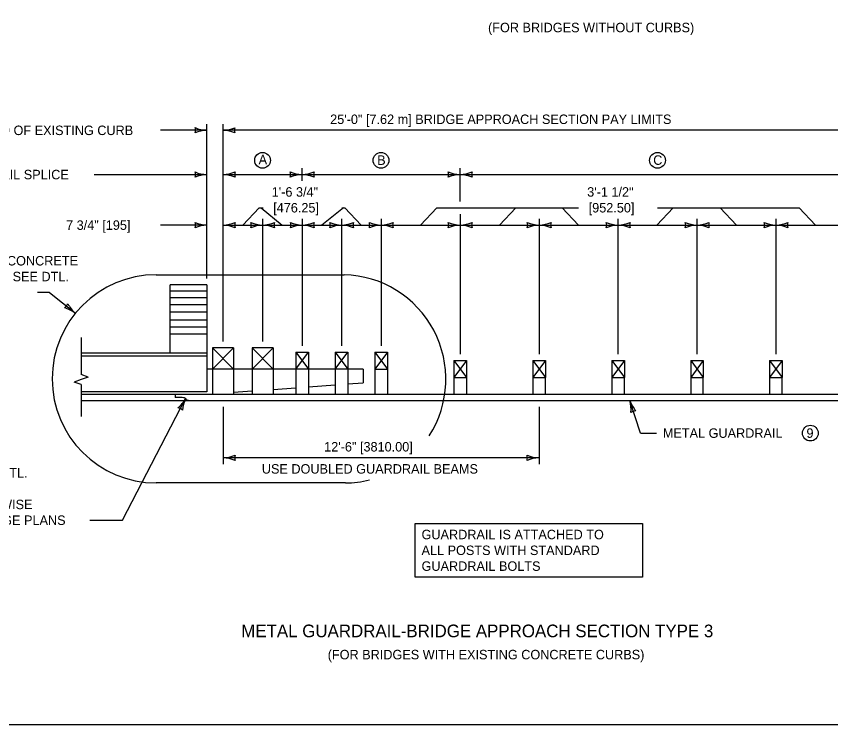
# Model space of a CAD drawing. Extents: x 49991.4 to 50021, y 49987.6 to 50011.4.
# Drawn here: x 50008.83 to 50013.99, y 49987.8 to 49992.28 of the extents above; entities that cross this region are included whole.
import ezdxf

# ---------------------------------------------------------------- set-up
doc = ezdxf.new("R2010")
doc.units = 0
for name, color, linetype in [('Level 1', 7, 'Continuous'), ('Level 2', 7, 'Continuous'), ('Level 3', 7, 'Continuous'), ('Level 4', 7, 'Continuous'), ('Level 6', 7, 'Continuous')]:
    doc.layers.add(name, color=color, linetype=linetype)

msp = doc.modelspace()

# ---------------------------------------------------------------- linework, layer by layer
at = {"layer": 'Level 1'}
for p, q in [((50010.0391, 49990.584), (50009.807, 49990.584)), ((50009.807, 49990.151), (50009.807, 49990.584)), ((50010.0391, 49990.584), (50010.0391, 49989.9066)), ((50010.0391, 49990.5438), (50009.807, 49990.5438)), ((50010.0391, 49990.5015), (50009.807, 49990.5015)), ((50010.0391, 49990.4569), (50009.807, 49990.4569)), ((50010.0391, 49990.4106), (50009.807, 49990.4106)), ((50010.0391, 49990.3606), (50009.807, 49990.3606)), ((50010.0391, 49990.316), (50009.807, 49990.316)), ((50010.0391, 49990.2718), (50009.807, 49990.2718)), ((50010.0391, 49990.151), (50009.244, 49990.151)), ((50010.2092, 49990.1843), (50010.0758, 49990.1843)), ((50010.0758, 49990.1843), (50010.0758, 49989.8909)), ((50010.0758, 49990.051), (50010.2092, 49990.1843)), ((50010.0758, 49990.1843), (50010.2092, 49990.051)), ((50010.2092, 49990.1843), (50010.2092, 49989.8909)), ((50010.4594, 49990.1844), (50010.326, 49990.1844)), ((50010.326, 49990.1844), (50010.326, 49989.8909)), ((50010.326, 49990.051), (50010.4594, 49990.1844)), ((50010.326, 49990.1844), (50010.4594, 49990.051)), ((50010.4594, 49990.1844), (50010.4594, 49989.8909)), ((50010.6028, 49990.1577), (50010.6028, 49989.8909)), ((50010.6028, 49990.1577), (50010.6829, 49990.1577)), ((50010.6028, 49990.051), (50010.6829, 49990.1577)), ((50010.6028, 49990.1577), (50010.6829, 49990.051)), ((50010.6829, 49990.1577), (50010.6829, 49989.8909)), ((50010.853, 49990.157), (50010.853, 49989.8909)), ((50010.853, 49990.157), (50010.933, 49990.157)), ((50010.853, 49990.051), (50010.933, 49990.157)), ((50010.853, 49990.157), (50010.933, 49990.051)), ((50010.933, 49990.157), (50010.933, 49989.8909)), ((50011.1031, 49990.1577), (50011.1031, 49990.051)), ((50011.1031, 49990.1577), (50011.1832, 49990.1577)), ((50011.1832, 49990.1577), (50011.1031, 49990.051)), ((50011.1031, 49990.1577), (50011.1832, 49990.051)), ((50011.1832, 49990.1577), (50011.1832, 49990.051)), ((50010.0391, 49990.1315), (50009.244, 49990.1315)), ((50011.6034, 49990.1043), (50011.6034, 49989.9976)), ((50011.6034, 49990.1043), (50011.6835, 49990.1043)), ((50011.6835, 49990.1043), (50011.6034, 49989.9976)), ((50011.6034, 49990.1043), (50011.6835, 49989.9976)), ((50011.6835, 49990.1043), (50011.6835, 49989.9976)), ((50012.1038, 49990.1043), (50012.1038, 49989.9976)), ((50012.1038, 49990.1043), (50012.1838, 49990.1043)), ((50012.1838, 49990.1043), (50012.1038, 49989.9976)), ((50012.1038, 49990.1043), (50012.1838, 49989.9976)), ((50012.1838, 49990.1043), (50012.1838, 49989.9976)), ((50012.604, 49990.1043), (50012.604, 49989.9976)), ((50012.604, 49990.1043), (50012.6841, 49990.1043)), ((50012.6841, 49990.1043), (50012.604, 49989.9976)), ((50012.604, 49990.1043), (50012.6841, 49989.9976)), ((50012.6841, 49990.1043), (50012.6841, 49989.9976)), ((50013.1043, 49990.1043), (50013.1043, 49989.9976)), ((50013.1043, 49990.1043), (50013.1844, 49990.1043)), ((50013.1844, 49990.1043), (50013.1043, 49989.9976)), ((50013.1043, 49990.1043), (50013.1844, 49989.9976)), ((50013.1844, 49990.1043), (50013.1844, 49989.9976)), ((50013.6046, 49990.1043), (50013.6046, 49989.9976)), ((50013.6046, 49990.1043), (50013.6847, 49990.1043)), ((50013.6847, 49990.1043), (50013.6046, 49989.9976)), ((50013.6046, 49990.1043), (50013.6847, 49989.9976)), ((50013.6847, 49990.1043), (50013.6847, 49989.9976)), ((50011.0289, 49990.051), (50010.0391, 49990.051)), ((50011.0289, 49990.051), (50011.0289, 49989.9642)), ((50011.1031, 49990.051), (50011.1832, 49990.051)), ((50011.1031, 49990.051), (50011.1031, 49989.8909)), ((50011.1832, 49990.051), (50011.1832, 49989.8909)), ((50011.6034, 49989.9976), (50011.6835, 49989.9976)), ((50011.6034, 49989.9976), (50011.6034, 49989.8909)), ((50011.6835, 49989.9976), (50011.6835, 49989.8909)), ((50012.1038, 49989.9976), (50012.1838, 49989.9976)), ((50012.1038, 49989.9976), (50012.1038, 49989.8909)), ((50012.1838, 49989.8909), (50012.1838, 49989.9976)), ((50012.604, 49989.9979), (50012.604, 49989.8909)), ((50012.604, 49989.9976), (50012.6841, 49989.9976)), ((50012.6841, 49989.8909), (50012.6841, 49989.9976)), ((50013.1043, 49989.9979), (50013.1043, 49989.8909)), ((50013.1043, 49989.9976), (50013.1844, 49989.9976)), ((50013.1844, 49989.8909), (50013.1844, 49989.9976)), ((50013.6046, 49989.9979), (50013.6046, 49989.8909)), ((50013.6046, 49989.9976), (50013.6847, 49989.9976)), ((50013.6847, 49989.8909), (50013.6847, 49989.9976)), ((50010.6829, 49989.9386), (50010.853, 49989.9512)), ((50010.933, 49989.9571), (50011.0289, 49989.9642)), ((50010.0391, 49989.9066), (50009.2441, 49989.9066)), ((50009.2441, 49989.8909), (50014.424, 49989.8909)), ((50009.839, 49989.8909), (50009.839, 49989.8702)), ((50010.0391, 49989.8909), (50010.0758, 49989.8936)), ((50010.2092, 49989.9035), (50010.326, 49989.9121)), ((50010.4594, 49989.922), (50010.6028, 49989.9326)), ((50009.2441, 49989.8508), (50014.424, 49989.8508)), ((50009.874, 49989.8702), (50009.839, 49989.8702))]:
    msp.add_line(p, q, dxfattribs=at)
msp.add_lwpolyline([(49999.3835, 49998.9992), (50016.7501, 49998.9992), (50016.7501, 49987.7988), (49999.3835, 49987.7988)], close=True, dxfattribs=at)
msp.add_spline([(50009.9238, 49989.8508), (50009.9175, 49989.8527), (50009.9113, 49989.8568), (50009.9061, 49989.863), (50009.902, 49989.8671), (50009.8927, 49989.8691), (50009.874, 49989.8702)], degree=3, dxfattribs=at)
at = {"layer": 'Level 2'}
msp.add_lwpolyline([(50011.3597, 49989.0731), (50012.7994, 49989.0731), (50012.7994, 49988.7331), (50011.3597, 49988.7331)], close=True, dxfattribs=at)
for centre in [(50010.3927, 49991.3723), (50011.1431, 49991.3723), (50012.8942, 49991.3723), (50013.8621, 49989.6453)]:
    msp.add_circle(centre, 0.05, dxfattribs=at)
at = {"layer": 'Level 3'}
for p, q in [((50010.0392, 49990.624), (50010.0392, 49991.6024)), ((50010.1426, 49990.2243), (50010.1426, 49991.6024)), ((50010.0392, 49991.5624), (50009.7455, 49991.5624)), ((50014.1448, 49991.5624), (50010.1426, 49991.5624)), ((50009.325, 49991.2823), (50010.0392, 49991.2823)), ((50010.1426, 49991.2823), (50010.6429, 49991.2823)), ((50010.6429, 49991.2423), (50010.6429, 49991.3223)), ((50010.6429, 49991.2823), (50011.6435, 49991.2823)), ((50011.6435, 49991.1123), (50011.6435, 49991.3223)), ((50011.6435, 49991.2823), (50014.1447, 49991.2823)), ((50010.3702, 49991.0723), (50010.2667, 49990.9623)), ((50010.3702, 49991.0723), (50010.3962, 49991.0723)), ((50010.3832, 49991.0723), (50010.517, 49990.9623)), ((50010.9051, 49991.0723), (50010.7676, 49990.9623)), ((50010.8957, 49991.0723), (50010.9144, 49991.0723)), ((50010.9144, 49991.0723), (50011.0179, 49990.9623)), ((50011.4967, 49991.0723), (50011.3932, 49990.9623)), ((50011.4967, 49991.0723), (50012.3943, 49991.0723)), ((50011.9969, 49991.0723), (50011.8934, 49990.9623)), ((50012.2904, 49991.0723), (50012.3939, 49990.9623)), ((50012.9929, 49991.0723), (50012.8894, 49990.9623)), ((50012.8938, 49991.0723), (50013.7912, 49991.0723)), ((50013.2909, 49991.0723), (50013.3944, 49990.9623)), ((50013.7912, 49991.0723), (50013.8947, 49990.9623)), ((50011.6434, 49991.0323), (50011.6434, 49990.1444)), ((50010.3927, 49991.0023), (50010.3927, 49990.2244)), ((50010.6429, 49991.0023), (50010.6429, 49990.1977)), ((50010.893, 49991.0023), (50010.893, 49990.197)), ((50011.1431, 49991.0023), (50011.1431, 49990.1977)), ((50012.1437, 49991.0023), (50012.1437, 49990.1444)), ((50012.6439, 49991.0023), (50012.6439, 49990.1444)), ((50013.1442, 49991.0023), (50013.1442, 49990.1444)), ((50013.6444, 49991.0023), (50013.6444, 49990.1444)), ((50010.0392, 49990.9623), (50009.7467, 49990.9623)), ((50010.1426, 49990.9623), (50010.3927, 49990.9623)), ((50010.3927, 49990.9623), (50010.6429, 49990.9623)), ((50010.6429, 49990.9623), (50010.893, 49990.9623)), ((50010.893, 49990.9623), (50011.1431, 49990.9623)), ((50011.1431, 49990.9623), (50011.6434, 49990.9623)), ((50011.6434, 49990.9623), (50012.1437, 49990.9623)), ((50012.1437, 49990.9623), (50012.6439, 49990.9623)), ((50012.6439, 49990.9623), (50013.1442, 49990.9623)), ((50013.1442, 49990.9623), (50013.6444, 49990.9623)), ((50013.6444, 49990.9623), (50014.1447, 49990.9623)), ((50009.0432, 49990.5366), (50008.9661, 49990.5366)), ((50009.0432, 49990.5366), (50009.2072, 49990.4038)), ((50009.5053, 49989.0937), (50009.9055, 49989.8637)), ((50012.7857, 49989.6453), (50012.7188, 49989.8508)), ((50010.1426, 49989.8108), (50010.1426, 49989.4487)), ((50012.1438, 49989.8108), (50012.1438, 49989.4487)), ((50012.7857, 49989.6453), (50012.8881, 49989.6453)), ((50012.1438, 49989.4887), (50010.1426, 49989.4887)), ((50009.2989, 49989.0937), (50009.5053, 49989.0937))]:
    msp.add_line(p, q, dxfattribs=at)
for centre, radius, start, end in [((50009.9142, 49991.5636), 0.0534, 341.5738, 17.2962), ((50010.0482, 49991.3354), 0.2271, 92.2623, 111.5122), ((50010.0503, 49991.7788), 0.2167, 246.891, 267.0745), ((50010.1314, 49991.7892), 0.2271, 272.8273, 292.0772), ((50010.1337, 49991.3458), 0.2167, 67.456, 87.6395), ((50010.2676, 49991.5624), 0.0534, 162.1388, 197.8612), ((50010.0481, 49991.4989), 0.2167, 247.456, 267.6395), ((50009.9142, 49991.2823), 0.0534, 342.1388, 17.8612), ((50010.0504, 49991.0554), 0.2271, 92.8273, 112.0772), ((50010.1311, 49991.5151), 0.2331, 272.8273, 292.0772), ((50010.1334, 49991.0601), 0.2224, 67.456, 87.6395), ((50010.2709, 49991.2823), 0.0548, 162.1388, 197.8612), ((50010.652, 49991.5046), 0.2224, 247.456, 267.6395), ((50010.5146, 49991.2823), 0.0548, 342.1388, 17.8612), ((50010.6544, 49991.0495), 0.2331, 92.8273, 112.0772), ((50010.6314, 49991.5151), 0.2331, 272.8273, 292.0772), ((50010.6337, 49991.0601), 0.2224, 67.456, 87.6395), ((50010.7711, 49991.2823), 0.0548, 162.1388, 197.8612), ((50011.6527, 49991.5046), 0.2224, 247.456, 267.6395), ((50011.5152, 49991.2823), 0.0548, 342.1388, 17.8612), ((50011.655, 49991.0495), 0.2331, 92.8273, 112.0772), ((50011.632, 49991.5151), 0.2331, 272.8273, 292.0772), ((50011.6343, 49991.0601), 0.2224, 67.456, 87.6395), ((50011.7718, 49991.2823), 0.0548, 162.1388, 197.8612), ((50010.0481, 49991.1789), 0.2167, 247.456, 267.6395), ((50009.9142, 49990.9623), 0.0534, 342.1388, 17.8612), ((50010.1311, 49991.1951), 0.2331, 272.8273, 292.0772), ((50010.2709, 49990.9623), 0.0548, 162.1388, 197.8612), ((50010.4017, 49991.1788), 0.2167, 247.456, 267.6395), ((50010.2677, 49990.9623), 0.0534, 342.1388, 17.8612), ((50010.3812, 49991.1951), 0.2331, 272.8273, 292.0772), ((50010.521, 49990.9623), 0.0548, 162.1388, 197.8612), ((50010.6518, 49991.1788), 0.2167, 247.456, 267.6395), ((50010.5179, 49990.9623), 0.0534, 342.1388, 17.8612), ((50010.6314, 49991.1951), 0.2331, 272.8273, 292.0772), ((50010.7711, 49990.9623), 0.0548, 162.1388, 197.8612), ((50010.9019, 49991.1788), 0.2167, 247.456, 267.6395), ((50010.768, 49990.9623), 0.0534, 342.1388, 17.8612), ((50010.8815, 49991.1951), 0.2331, 272.8273, 292.0772), ((50011.0213, 49990.9623), 0.0548, 162.1388, 197.8612), ((50011.1521, 49991.1788), 0.2167, 247.456, 267.6395), ((50011.0181, 49990.9623), 0.0534, 342.1388, 17.8612), ((50011.1316, 49991.1951), 0.2331, 272.8273, 292.0772), ((50011.2714, 49990.9623), 0.0548, 162.1388, 197.8612), ((50011.6523, 49991.1788), 0.2167, 247.456, 267.6395), ((50011.5184, 49990.9623), 0.0534, 342.1388, 17.8612), ((50011.6319, 49991.1951), 0.2331, 272.8273, 292.0772), ((50011.7717, 49990.9623), 0.0548, 162.1388, 197.8612), ((50012.1526, 49991.1788), 0.2167, 247.456, 267.6395), ((50012.0187, 49990.9623), 0.0534, 342.1388, 17.8612), ((50012.1322, 49991.1951), 0.2331, 272.8273, 292.0772), ((50012.2719, 49990.9623), 0.0548, 162.1388, 197.8612), ((50012.6528, 49991.1788), 0.2167, 247.456, 267.6395), ((50012.5189, 49990.9623), 0.0534, 342.1388, 17.8612), ((50012.6324, 49991.1951), 0.2331, 272.8273, 292.0772), ((50012.7722, 49990.9623), 0.0548, 162.1388, 197.8612), ((50013.1531, 49991.1788), 0.2167, 247.456, 267.6395), ((50013.0192, 49990.9623), 0.0534, 342.1388, 17.8612), ((50013.1327, 49991.1951), 0.2331, 272.8273, 292.0772), ((50013.2725, 49990.9623), 0.0548, 162.1388, 197.8612), ((50013.6534, 49991.1788), 0.2167, 247.456, 267.6395), ((50013.5195, 49990.9623), 0.0534, 342.1388, 17.8612), ((50013.6329, 49991.1951), 0.2331, 272.8273, 292.0772), ((50013.7727, 49990.9623), 0.0548, 162.1388, 197.8612), ((50010.0504, 49990.7354), 0.2271, 92.8273, 112.0772), ((50010.1334, 49990.7401), 0.2224, 67.456, 87.6395), ((50010.4039, 49990.7355), 0.2271, 92.8273, 112.0772), ((50010.3836, 49990.7401), 0.2224, 67.456, 87.6395), ((50010.6541, 49990.7355), 0.2271, 92.8273, 112.0772), ((50010.6337, 49990.7401), 0.2224, 67.456, 87.6395), ((50010.9042, 49990.7355), 0.2271, 92.8273, 112.0772), ((50010.8838, 49990.7401), 0.2224, 67.456, 87.6395), ((50011.1543, 49990.7355), 0.2271, 92.8273, 112.0772), ((50011.134, 49990.7401), 0.2224, 67.456, 87.6395), ((50011.6546, 49990.7355), 0.2271, 92.8273, 112.0772), ((50011.6342, 49990.7401), 0.2224, 67.456, 87.6395), ((50012.1549, 49990.7355), 0.2271, 92.8273, 112.0772), ((50012.1345, 49990.7401), 0.2224, 67.456, 87.6395), ((50012.6551, 49990.7355), 0.2271, 92.8273, 112.0772), ((50012.6348, 49990.7401), 0.2224, 67.456, 87.6395), ((50013.1554, 49990.7355), 0.2271, 92.8273, 112.0772), ((50013.135, 49990.7401), 0.2224, 67.456, 87.6395), ((50013.6556, 49990.7355), 0.2271, 92.8273, 112.0772), ((50013.6353, 49990.7401), 0.2224, 67.456, 87.6395), ((50009.1076, 49990.4845), 0.0548, 303.1426, 338.865), ((50009.3541, 49990.5707), 0.2223, 208.4598, 228.6433), ((50009.0697, 49990.2157), 0.233, 53.8311, 73.081), ((50009.7175, 49989.9715), 0.2167, 309.9961, 330.1796), ((50010.112, 49989.769), 0.2271, 155.3674, 174.6172), ((50012.5101, 49989.7923), 0.2167, 355.4765, 15.66), ((50012.9311, 49989.9317), 0.2271, 200.8478, 220.0976), ((50009.8479, 49989.7528), 0.0534, 44.6789, 80.4012), ((50012.7575, 49989.732), 0.0534, 90.1593, 125.8816), ((50010.1311, 49989.7215), 0.2331, 272.8273, 292.0772), ((50010.1334, 49989.2664), 0.2225, 67.456, 87.6395), ((50010.2709, 49989.4887), 0.0548, 162.1388, 197.8612), ((50012.153, 49989.7109), 0.2225, 247.456, 267.6395), ((50012.0155, 49989.4887), 0.0548, 342.1388, 17.8612), ((50012.1553, 49989.2558), 0.2331, 92.8273, 112.0772)]:
    msp.add_arc(centre, radius, start, end, dxfattribs=at)
at = {"layer": 'Level 4'}
for p, q in [((50009.7196, 49990.6483), (50010.9094, 49990.6483)), ((50010.9185, 49989.3297), (50009.7196, 49989.3297))]:
    msp.add_line(p, q, dxfattribs=at)
for centre, radius, start, end in [((50009.7196, 49989.989), 0.6593, 90, 270), ((50010.8923, 49989.9869), 0.6615, 327.2133, 88.5245), ((50010.9185, 49989.9393), 0.6096, 270, 284.3678)]:
    msp.add_arc(centre, radius, start, end, dxfattribs=at)
at = {"layer": 'Level 6'}
for p, q in [((50009.244, 49990.251), (50009.244, 49990.0159)), ((50009.2886, 49990.0001), (50009.244, 49990.0159)), ((50009.2886, 49990.0001), (50009.2441, 49989.9843)), ((50009.2441, 49989.9843), (50009.1995, 49989.9685)), ((50009.2441, 49989.9527), (50009.1995, 49989.9685)), ((50009.2441, 49989.9527), (50009.2441, 49989.7506))]:
    msp.add_line(p, q, dxfattribs=at)

# ---------------------------------------------------------------- texts
at = {"layer": 'Level 2'}
for s, height, p in [('(FOR BRIDGES WITHOUT CURBS)', 0.06, (50011.8208, 49992.1835)), ('25\'-0" [7.62 m] BRIDGE APPROACH SECTION PAY LIMITS', 0.06, (50010.8207, 49991.6024)), ('END OF EXISTING CURB', 0.06, (50008.6237, 49991.5324)), ('A', 0.06, (50010.3676, 49991.3475)), ('B', 0.06, (50011.1186, 49991.3436)), ('C', 0.06, (50012.8671, 49991.344)), ('¡ RAIL SPLICE', 0.06, (50008.6304, 49991.2523)), ('1\'-6 3/4"', 0.06, (50010.4507, 49991.1423)), ('3\'-1 1/2"', 0.06, (50012.4488, 49991.1423)), ('[476.25]', 0.06, (50010.46, 49991.0423)), ('[952.50]', 0.06, (50012.4581, 49991.0423)), ('7 3/4" [195]', 0.06, (50009.1482, 49990.9323)), ('FOR TAPERED CONCRETE', 0.06, (50008.1808, 49990.7066)), ('CURB DETAILS, SEE DTL.', 0.06, (50008.1808, 49990.6066)), ('METAL GUARDRAIL', 0.06, (50012.9281, 49989.6153)), ('9', 0.06, (50013.8376, 49989.6153)), ('12\'-6" [3810.00]', 0.06, (50010.7829, 49989.5287)), ('RWE02a-b (SEE DTL.', 0.06, (50008.1062, 49989.3637)), ('USE DOUBLED GUARDRAIL BEAMS', 0.06, (50010.3881, 49989.3887)), ('UNLESS OTHERWISE', 0.06, (50008.1062, 49989.1637)), ('NOTED ON BRIDGE PLANS', 0.06, (50008.1062, 49989.0637)), ('GUARDRAIL IS ATTACHED TO', 0.06, (50011.3997, 49988.9731)), ('ALL POSTS WITH STANDARD', 0.06, (50011.3997, 49988.8731)), ('GUARDRAIL BOLTS', 0.06, (50011.3997, 49988.7731)), ('METAL GUARDRAIL-BRIDGE APPROACH SECTION TYPE 3', 0.08, (50010.2575, 49988.3527)), ('(FOR BRIDGES WITH EXISTING CONCRETE CURBS)', 0.06, (50010.8053, 49988.2127))]:
    msp.add_text(s, height=height, dxfattribs=at).set_placement(p)

doc.saveas('drawing.dxf')
